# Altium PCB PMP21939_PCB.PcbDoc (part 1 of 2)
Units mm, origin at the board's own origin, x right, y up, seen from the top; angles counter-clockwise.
Board outline 80 x 87.63 mm, 4 copper layers (Top Layer, Signal Layer 1, Signal Layer 2, Bottom Layer), stack 1.565 mm thick; 129 components, 68 nets, 325 pads, 91 vias.
Unrouted connection lines stored in the file: 2.
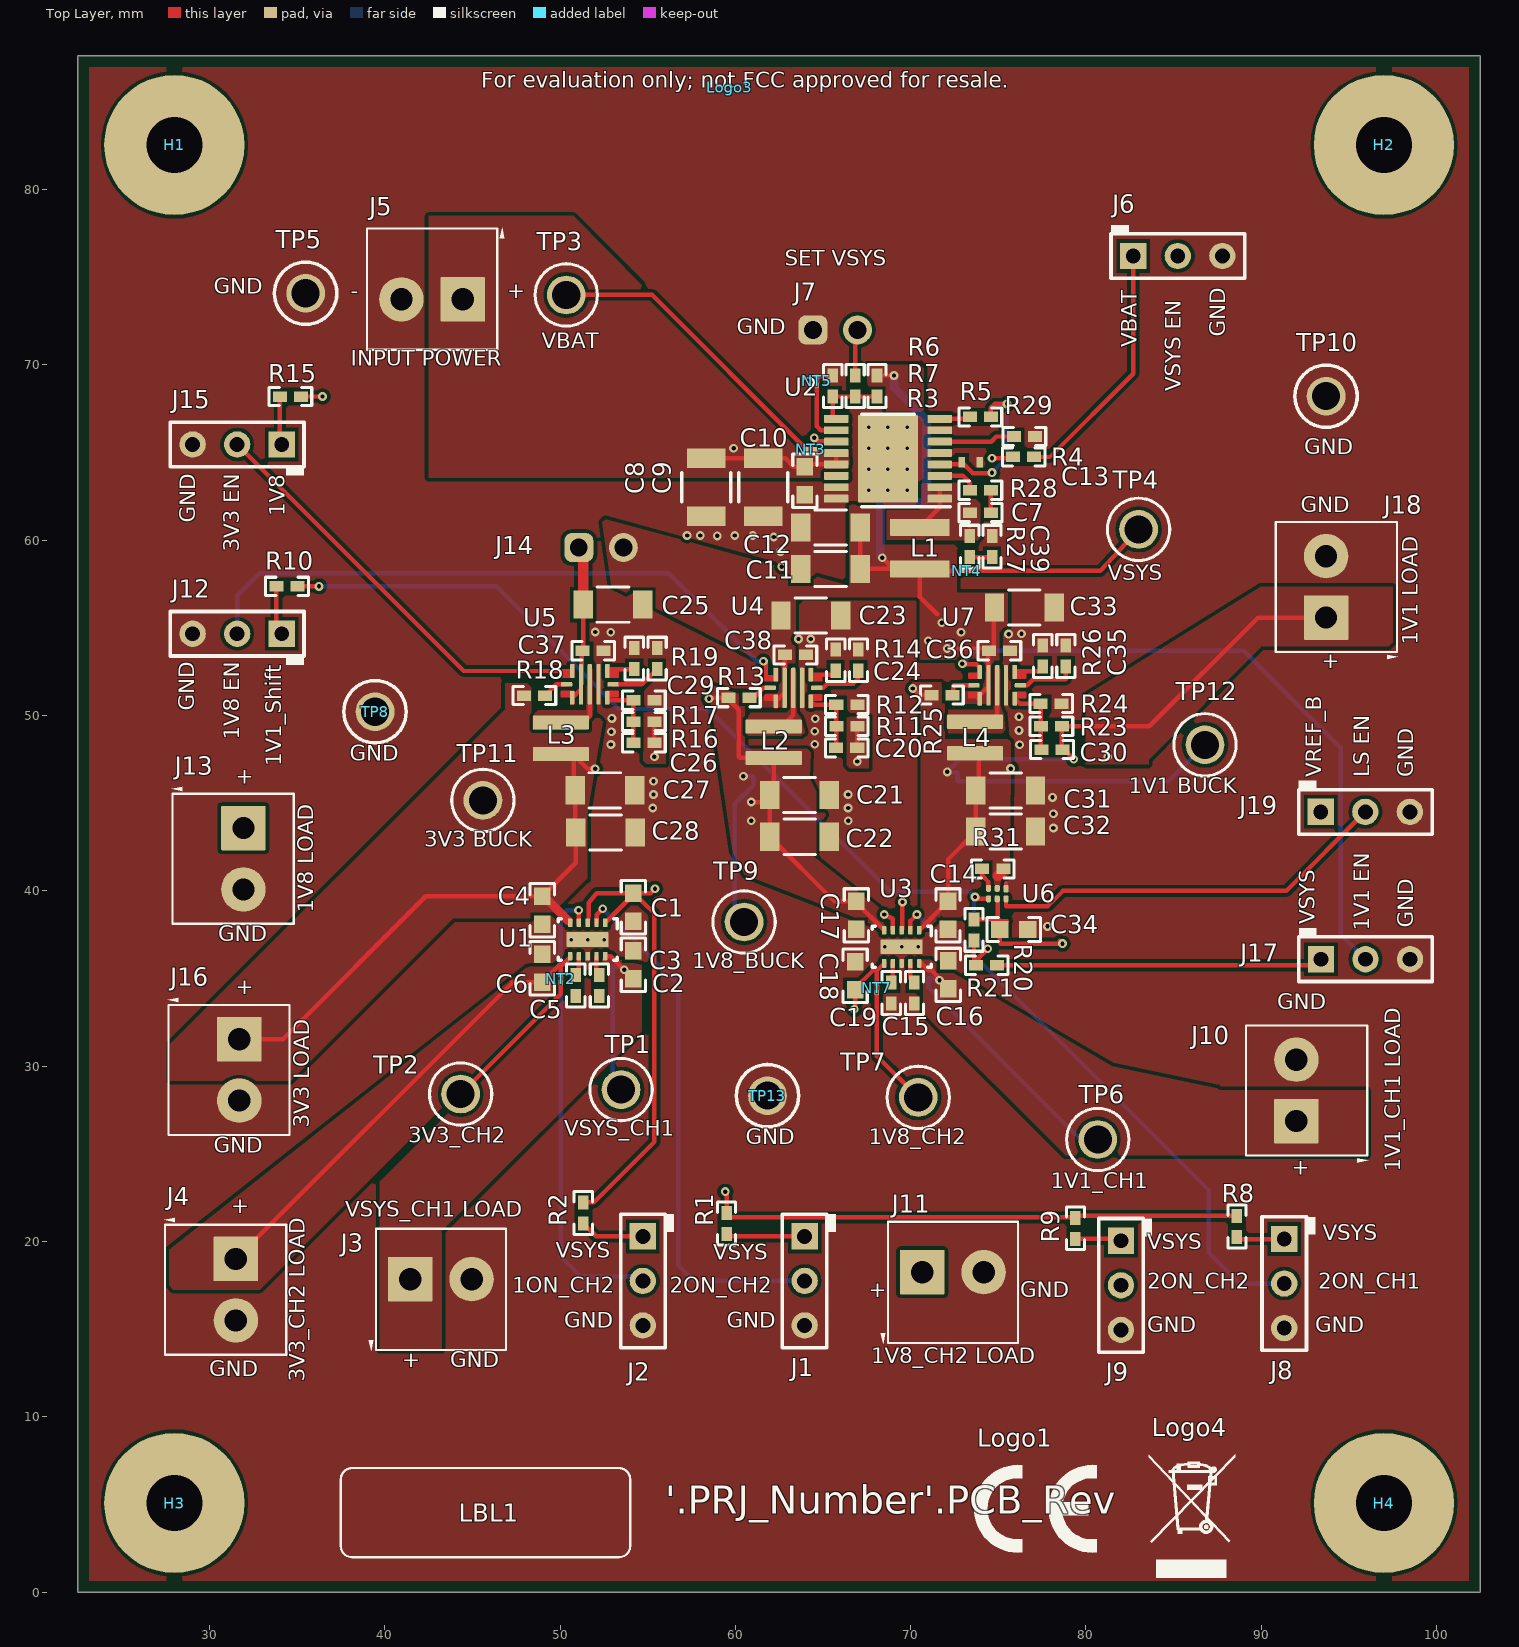
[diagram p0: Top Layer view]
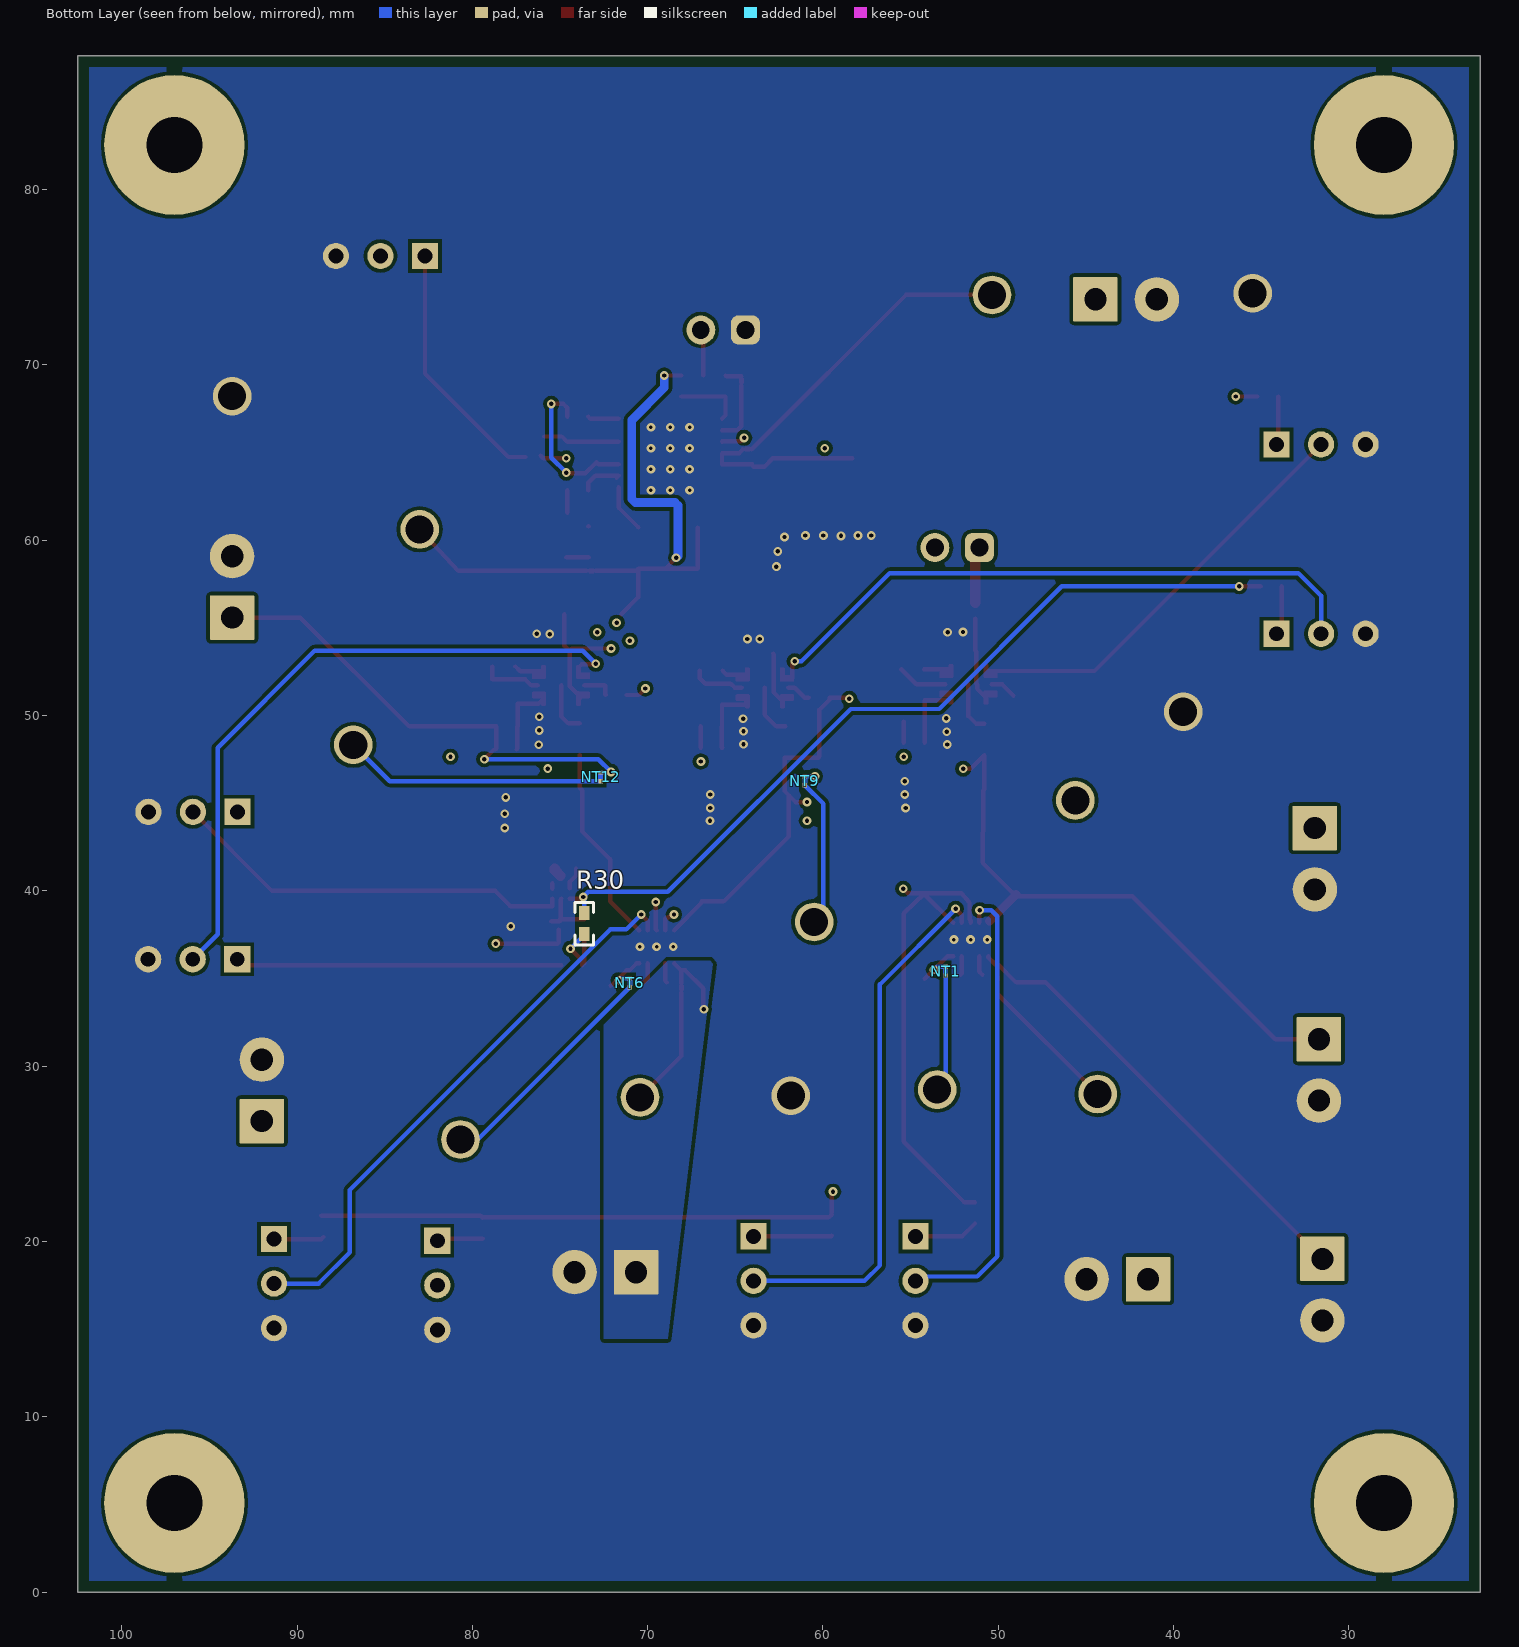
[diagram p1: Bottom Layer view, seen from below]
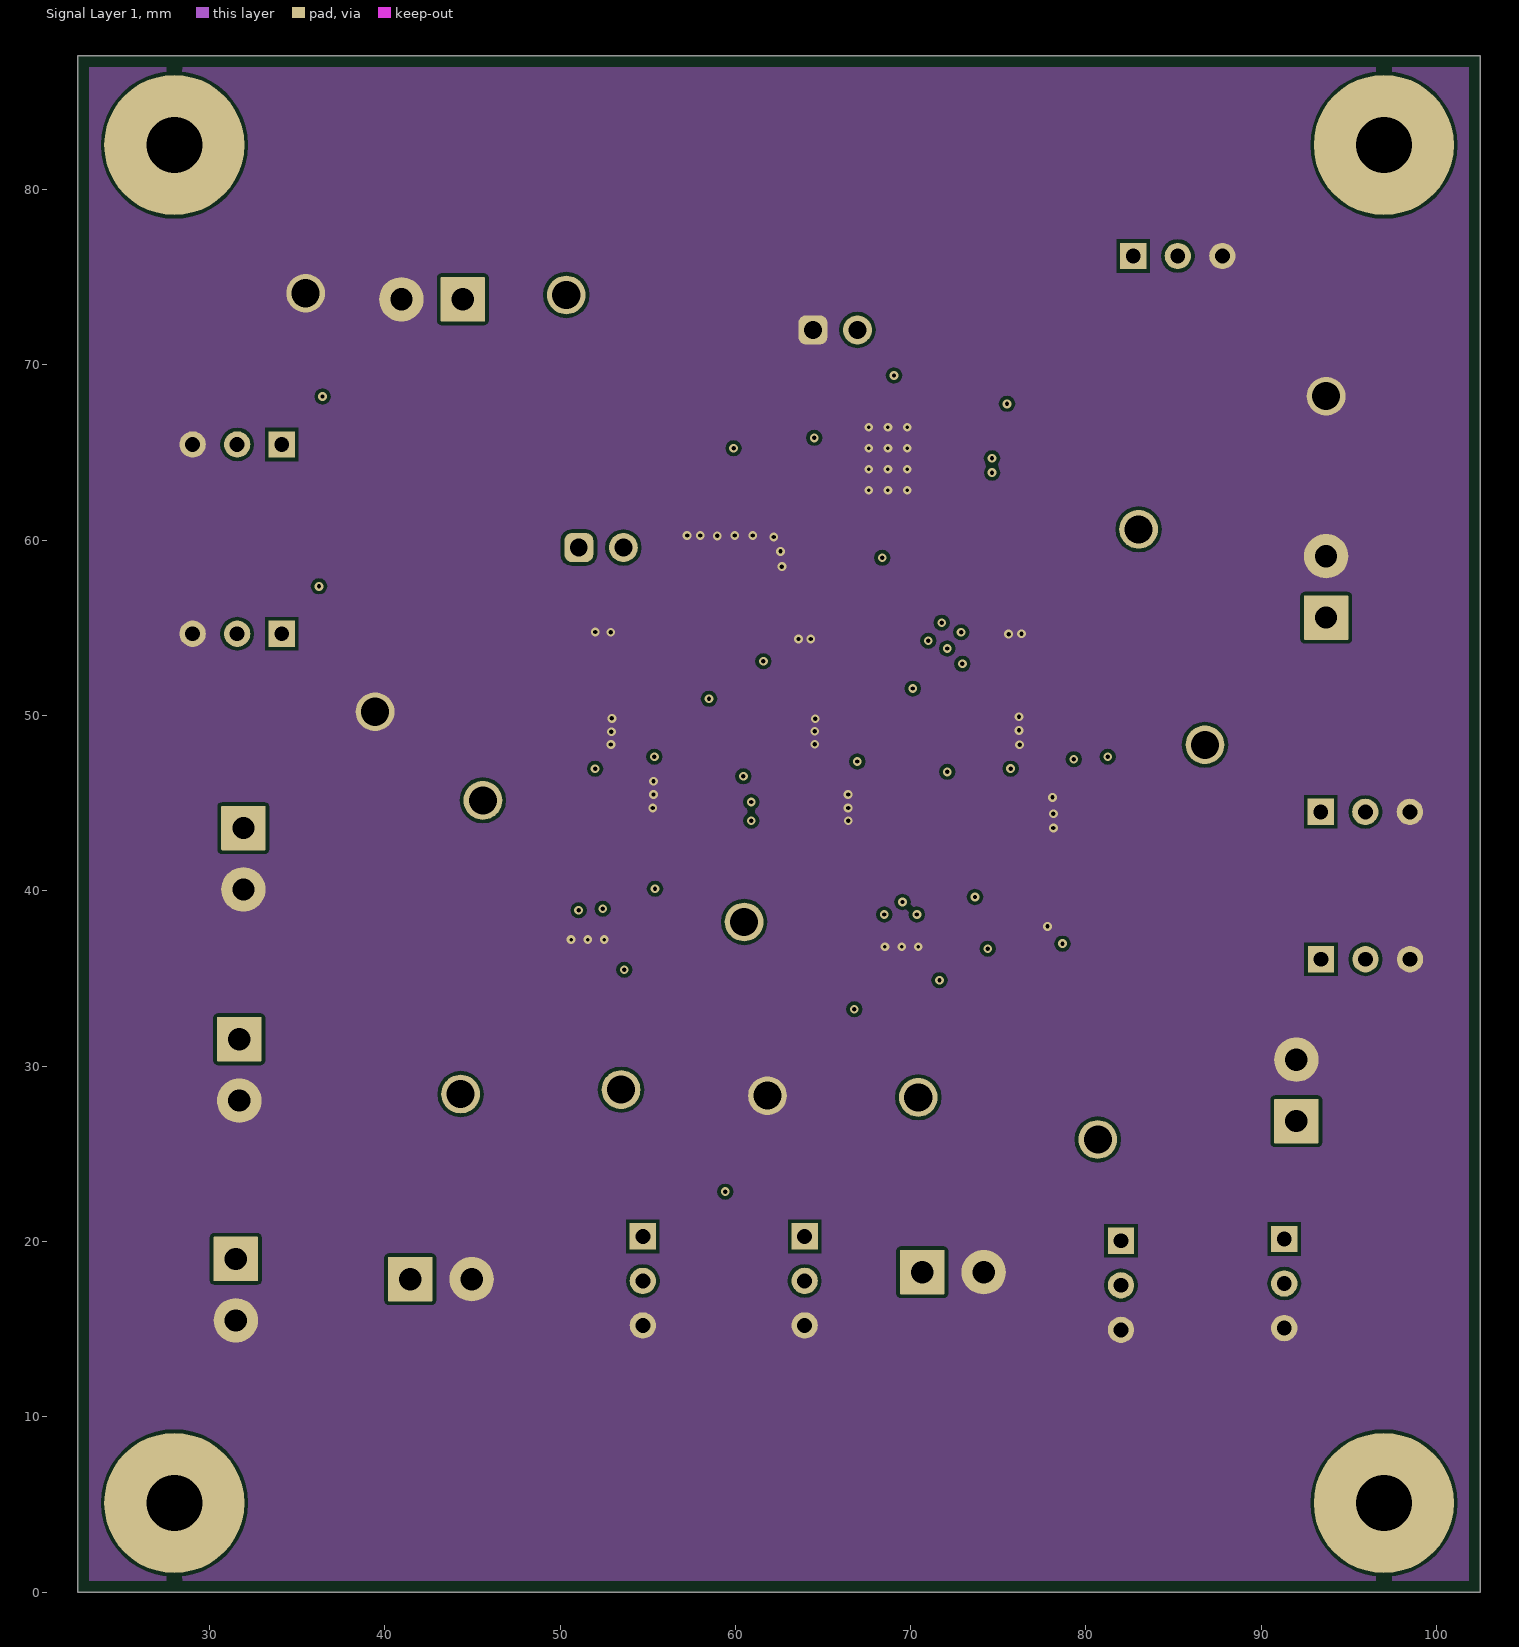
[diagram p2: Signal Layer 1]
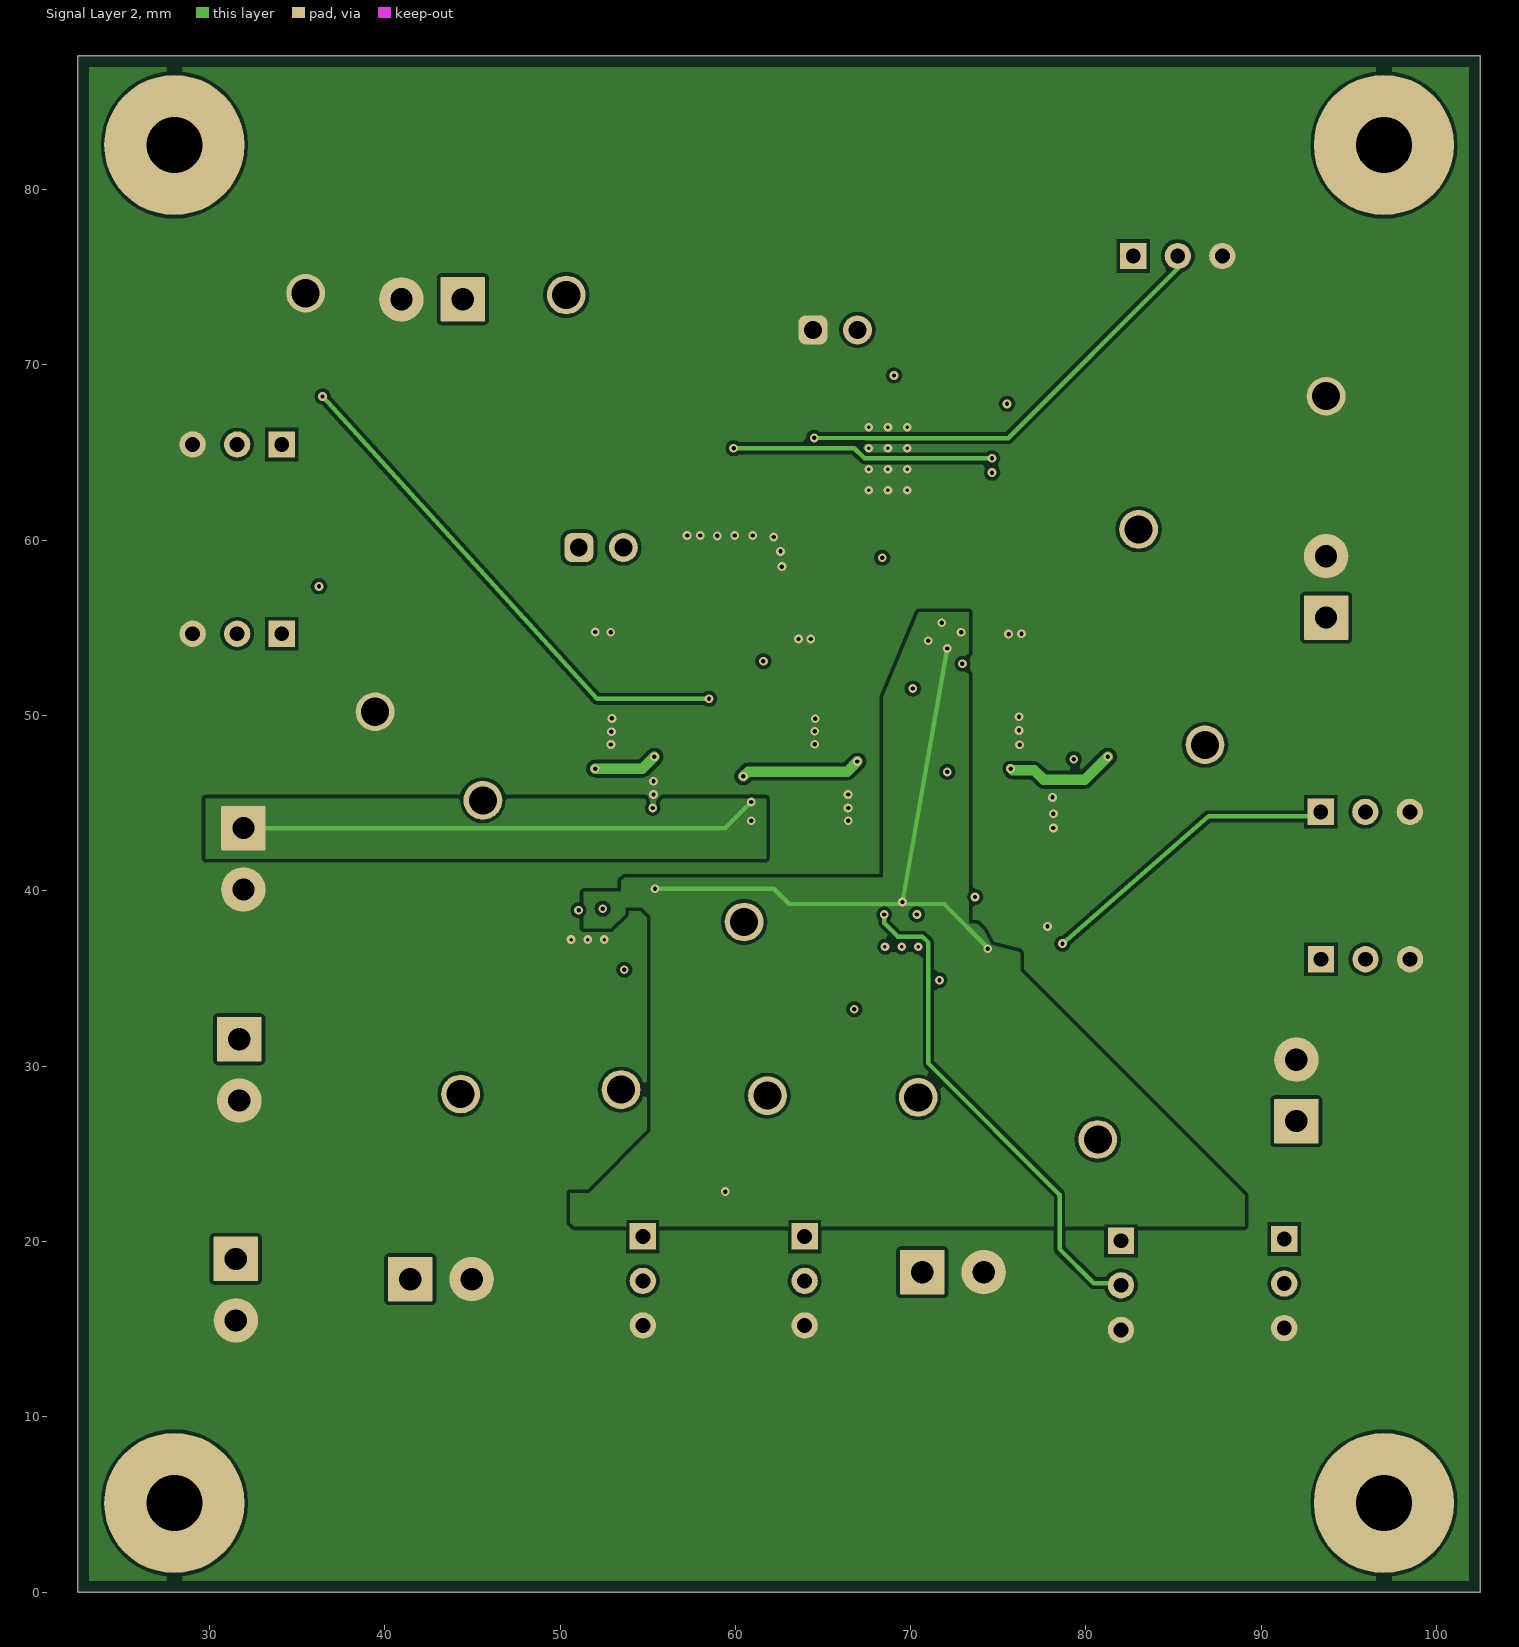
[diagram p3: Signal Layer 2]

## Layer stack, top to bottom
Top Solder: solder mask 0.0102, Solder Resist, Dk 3.5
Top Layer: signal copper 0.0356
Dielectric 2: dielectric 0.2032, Dk 4.2
Signal Layer 1: signal copper 0.0356
Dielectric1: core 1.016, FR-4, Dk 4.8
Signal Layer 2: signal copper 0.0356
Dielectric 3: dielectric 0.2032, Dk 4.2
Bottom Layer: signal copper 0.0356
Bottom Solder: solder mask 0.0102, Solder Resist, Dk 3.5

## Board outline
22.5,0 102.5,0 102.5,87.63 22.5,87.63

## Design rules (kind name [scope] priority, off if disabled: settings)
AcuteAngle [All] p1: minimum=4.50000000000000E+0001 checktracksonly=FALSE
AssemblyTestPointUsage [All] p1: valid=2
BoardOutlineClearance BoardOutlineClearance_MountingHoles [OnCopper and InComponentClass('Mounting Holes')] p1: gap=1 ignorepadtopadclearanceinfootprint=FALSE
BoardOutlineClearance BoardOutlineClearance_Poly [OnCopper and IsPoly] p2: gap=0.635 ignorepadtopadclearanceinfootprint=FALSE
BoardOutlineClearance [OnCopper and Not InComponentClass('Logo') and not InComponentClass('FiducialMark') and not InRegion(1000,500,4000,800) and not InPoly] p3: gap=1.905 ignorepadtopadclearanceinfootprint=FALSE
Clearance Clearance_Keepouts [((IsTrack Or IsArc) And Not InPoly) And IsFree and IsKeepOut vs ((IsTrack Or IsArc) And Not InPoly) And IsFree and IsKeepOut] p1: gap=0 ignorepadtopadclearanceinfootprint=FALSE
Clearance Clearance_Poly [InPolygon] p2: gap=0.2 ignorepadtopadclearanceinfootprint=TRUE
Clearance Clearance_FiducialMark [IsKeepOut and InComponentClass('FiducialMark') vs IsPad and InComponentClass('FiducialMark')] p3: gap=0 ignorepadtopadclearanceinfootprint=FALSE
Clearance [All] p4: gap=0.2 ignorepadtopadclearanceinfootprint=TRUE
ComponentClearance ComponentClearance_MountingHoles_FiducialMarks [InComponentClass('Mounting Holes') vs InComponentClass('FiducialMark')] p1: gap=1.27 collisioncheckmode=3 verticalgap=0.254 showdistances=FALSE
ComponentClearance ComponentClearance_Shunt [InComponentClass('Header') vs InComponentClass('Shunt')] p2: gap=0 collisioncheckmode=3 verticalgap=0 showdistances=FALSE
ComponentClearance ComponentClearance_Logo [InComponentClass('Logo')] p3: gap=1.27 collisioncheckmode=3 verticalgap=0.254 showdistances=FALSE
ComponentClearance ComponentClearance_ScrewToNut [(HasFootprint('NY PMS 440 0025 PH')) vs (HasFootprint('Keystone_1902C'))] p4: gap=0.127 collisioncheckmode=3 verticalgap=0.254 showdistances=FALSE
ComponentClearance ComponentClearance_MountingHoles [InComponentClass('Mounting Holes')] p5: gap=6.35 collisioncheckmode=3 verticalgap=2540 showdistances=FALSE
ComponentClearance ComponentClearance_SmallPassives [HasFootprint('0201*') or HasFootprint('0402*') or HasFootprint('0508') or HasFootprint('0603*') or HasFootprint('0612') or HasFootprint('0805*') or HasFootprint('0815*') or HasFootprint('0830*') or HasFootprint('1206*') or HasFootprint('1210*') or HasFootprint('1808*') or HasFootprint('1812*') or HasFootprint('1825*') or HasFootprint('2010*') or HasFootprint('2220*') or HasFootprint('2225*') or HasFootprint('2512*') or HasFootprint('2728*') or HasFootprint('3518*') vs HasFootprint('0201*') or HasFootprint('0402*') or HasFootprint('0508') or HasFootprint('0603*') or HasFootprint('0612') or HasFootprint('0805*') or HasFootprint('0815*') or HasFootprint('0830*') or HasFootprint('1206*') or HasFootprint('1210*') or HasFootprint('1808*') or HasFootprint('1812*') or HasFootprint('1825*') or HasFootprint('2010*') or HasFootprint('2220*') or HasFootprint('2225*') or HasFootprint('2512*') or HasFootprint('2728*') or HasFootprint('3518*')] p6: gap=0.38 collisioncheckmode=3 verticalgap=0.254 showdistances=FALSE
ComponentClearance ComponentClearance_THtoSMT [IsThruComponent vs IsSMTComponent] p7: gap=1.016 collisioncheckmode=3 verticalgap=0.762 showdistances=FALSE
ComponentClearance ComponentClearance_THtoTH [IsThruComponent vs IsThruComponent] p8: gap=0.762 collisioncheckmode=3 verticalgap=0.762 showdistances=FALSE
ComponentClearance [All] p9: gap=0.1 collisioncheckmode=3 verticalgap=0.1 showdistances=FALSE
DiffPairsRouting [All] p1: maxlimit=2.54 minlimit=0.254 mostfreqgap=0.254 toplayer_minwidth=0.381 toplayer_maxwidth=0.381 toplayer_prefwidth=0.381 midlayer1_minwidth=0.381 midlayer1_maxwidth=0.381 midlayer1_prefwidth=0.381 midlayer2_minwidth=0.381 midlayer2_maxwidth=0.381 midlayer2_prefwidth=0.381 bottomlayer_minwidth=0.381 bottomlayer_maxwidth=0.381 bottomlayer_prefwidth=0.381 maxuncoupledlength=25.4
FabricationTestPointUsage TestPointUsage [All] p1: valid=2 allowmultiple=FALSE
FabricationTestpoint Testpoint [All] p1: side=3 testpointundercomponent=TRUE minsize=1.016 maxsize=2.54 preferedsize=1.524 minholesize=0 maxholesize=1.016 preferedholesize=0.813 testpointgrid=0.025 allowsidetop=TRUE allowsidebottom=TRUE usegrid=TRUE gridtolerance=0
FanoutControl Fanout_LCC [IsLCC] p1: bgadir=Out bgaviamode=Centered fanoutstyle=Auto fanoutdirection=Alternating viagrid=0.025 // Fanout_LCC (Default Rule)
FanoutControl Fanout_BGA [IsBGA] p2: bgadir=Out bgaviamode=Centered fanoutstyle=Auto fanoutdirection=Alternating viagrid=0.025 // Fanout_BGA (Default Rule)
FanoutControl Fanout_Default [All] p4: bgadir=Out bgaviamode=Centered fanoutstyle=Auto fanoutdirection=Alternating viagrid=0.025 // Fanout_Default (Default Rule)
FanoutControl Fanout_Small [(CompPinCount < 5)] p5: bgadir=Out bgaviamode=Centered fanoutstyle=Auto fanoutdirection=OutThenIn viagrid=0.025 // Fanout_Small (Default Rule)
HoleSize [All] p1: absolutevalues=TRUE maxlimit=6.375 minlimit=0.2 maxpercent=80.000 minpercent=20.000
MinimumAnnularRing MinimumAnnularRing_ThermalPadVias [IsVia and InAnyComponent] p1: minimumring=0.15
MinimumAnnularRing [All] p2: minimumring=0.2
MinimumSolderMaskSliver MinimumSolderMaskSliver_Logo [InComponentClass('Logo') vs InComponentClass('Logo')] p1: minsoldermaskwidth=0.018
MinimumSolderMaskSliver [All] p2: minsoldermaskwidth=0.1
PlaneClearance [All] p1: clearance=0.1
PlaneConnect [All] p1: planeconnectstyle=Direct reliefexpansion=0.254 reliefentries=4 reliefconductorwidth=0.254 reliefairgap=0.254
PolygonConnect [All] p1: connectstyle=Direct reliefconductorwidth=0.254 reliefentries=4 polygonreliefangle="90 Angle" airgapwidth=0.254
RoutingVias ThermalPadVias [IsVia and InAnyComponent] p1: holewidth=0.2 width=0.5 viastyle="Through Hole" minholewidth=0.2 minwidth=0.5 maxholewidth=0.33 maxwidth=0.6
RoutingVias [All] p2: holewidth=0.406 width=0.864 viastyle="Through Hole" minholewidth=0.2 minwidth=0.66 maxholewidth=1.016 maxwidth=1.651
SilkToBoardRegionClearance [Not ((IsComment or IsDesignator) And (Hide <> 'False')) and not InRegion(1000,500,4000,800)] p1:
SilkToSilkClearance SilkToSilkClearance_Pb-FreeLogo [(HasFootprint('Pb-Free_Overlay_Medium') OR HasFootprint('Pb-Free_Overlay_Small')) vs (HasFootprint('Pb-Free_Overlay_Medium') OR HasFootprint('Pb-Free_Overlay_Small'))] p1: silktosilkclearance=0
SilkToSilkClearance [All] p2: silktosilkclearance=0.1
SilkToSolderMaskClearance SilkToComponentPadClearance [(IsPad or IsFill or IsRegion) and InAnycomponent] p1: minsilkscreentomaskgap=0.127 clearancetoexposedcopper=TRUE
SilkToSolderMaskClearance "Silk to Solder Mask Opening" [All] p2: minsilkscreentomaskgap=0.1 clearancetoexposedcopper=FALSE
SolderMaskExpansion [All] p1: expansion=0.05
UnRoutedNet [All] p1: checkbadconnections=TRUE
Width [All] p1: maxlimit=2.54 minlimit=0.152 preferedwidth=0.254 checkconnectedcopper=TRUE
13 further rules are at their usual default settings.

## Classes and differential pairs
component class "PMP21939_Load Converters": C20 C21 C22 C23 C24 C25 C26 C27 C28 C29 C30 C31 C32 C33 C34 C35 C36 C37 C38 J12 J13 J14 J15 J16 J17 J18 J19 L2 L3 L4 NT9 NT12 R10 R11 R12 R13 R14 R15 R16 R17 R18 R19 R20 R21 R23 R24 R25 R26 R30 R31 TP9 TP10 TP11 TP12 TP13 U4 U5 U6 U7
component class "PMP21939_Bus+Load Switches": C1 C2 C3 C4 C5 C6 C7 C8 C9 C10 C11 C12 C13 C14 C15 C16 C17 C18 C19 C39 J1 J2 J3 J4 J5 J6 J7 J8 J9 J10 J11 L1 NT1 NT2 NT3 NT4 NT5 NT6 NT7 R1 R2 R3 R4 R5 R6 R7 R8 R9 R27 R28 R29 TP1 TP2 TP3 TP4 TP5 TP6 TP7 TP8 U1 U2 U3
component class Header: J1 J2 J6 J7 J8 J9 J12 J14 J15 J17 J19
component class "Mounting Holes": H1 H2 H3 H4
component class Hardware: H1 H2 H3 H4 LBL1 Logo1 Logo3 Logo4
component class Label: LBL1

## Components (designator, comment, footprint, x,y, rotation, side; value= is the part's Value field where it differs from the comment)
C1 "GCM188R71C105MA64D" 0603 54.186,39.074 r270 top value=1uF
C2 "CGA2B2X7R1H102K050BA" 0402 52.244,34.601 r270 top value=1000pF
C3 "CGA3E2X7R1E104K080AA" 0603 54.186,35.78 r90 top value=0.1uF
C4 "GCM188R71C105MA64D" 0603 48.985,38.893 r270 top value=1uF
C5 "CGA2B2X7R1H102K050BA" 0402 50.899,34.605 r270 top value=1000pF
C6 "CGA3E2X7R1E104K080AA" 0603 48.985,35.579 r90 top value=0.1uF
C7 "C1005X7R1C224K050BC" 0402 73.985,61.578 r180 top value=0.22uF
C8 "CGA6P3X7R1H475K250AB" 1210_280 58.338,63.026 r270 top value=4.7uF
C9 "CGA6P3X7R1H475K250AB" 1210_280 61.588,63.026 r270 top value=4.7uF
C10 "CGA3E2X7R1E104K080AA" 0603 63.965,63.4 r270 top value=0.1uF
C11 "GCM31CR71A226KE02" 1206_180 65.432,58.366 r180 top value=22uF
C12 "GCM31CR71A226KE02" 1206_180 65.432,60.719 r180 top value=22uF
C13 "GCM155C71A105KE38D" 0402_070 73.432,64.45 r0 top value=1uF
C14 "GCM188R71C105MA64D" 0603 72.136,38.599 r270 top value=1uF
C15 "CGA2B2X7R1H102K050BA" 0402 70.219,34.176 r270 top value=1000pF
C16 "CGA3E2X7R1E104K080AA" 0603 72.146,35.205 r90 top value=0.1uF
C17 "GCM188R71C105MA64D" 0603 66.908,38.599 r270 top value=1uF
C18 "CGA3E2X7R1E104K080AA" 0603 66.834,35.155 r90 top value=0.1uF
C19 "CGA2B2X7R1H102K050BA" 0402 68.9,34.176 r270 top value=1000pF
C20 "CGA2B2NP01H220J050BA" 0402 66.357,48.152 r180 top value=22pF
C21 "GCM31CR71A226KE02" 1206_180 63.662,45.469 r0 top value=22uF
C22 "GCM31CR71A226KE02" 1206_180 63.667,43.088 r0 top value=22uF
C23 "GCM31CR71A226KE02" 1206_180 64.312,55.719 r0 top value=22uF
C24 "CGA2B3X7S2A472K050BB" 0402 67.026,53.157 r90 top value=4700pF
C25 "GCM31CR71A226KE02" 1206_180 53.024,56.324 r0 top value=22uF
C26 "CGA2B2NP01H220J050BA" 0402 54.786,48.448 r180 top value=22pF
C27 "GCM31CR71A226KE02" 1206_180 52.562,45.739 r0 top value=22uF
C28 "GCM31CR71A226KE02" 1206_180 52.597,43.333 r0 top value=22uF
C29 "CGA2B3X7S2A472K050BB" 0402 55.538,53.251 r90 top value=4700pF
C30 "CGA2B2NP01H220J050BA" 0402 78.063,48.064 r180 top value=22pF
C31 "GCM31CR71A226KE02" 1206_180 75.424,45.73 r0 top value=22uF
C32 "GCM31CR71A226KE02" 1206_180 75.421,43.38 r0 top value=22uF
C33 "GCM31CR71A226KE02" 1206_180 76.492,56.176 r0 top value=22uF
C34 "CGA3E2X7R1E104K080AA" 0603 75.879,37.796 r0 top value=0.1uF
C35 "CGA2B3X7S2A472K050BB" 0402 78.858,53.399 r90 top value=4700pF
C36 "CGA2B3X7R1H104K050BB" 0402 75.067,53.699 r0 top value=0.1uF
C37 "CGA2B3X7R1H104K050BB" 0402 51.894,53.699 r0 top value=0.1uF
C38 "CGA2B3X7R1H104K050BB" 0402 63.426,53.457 r0 top value=0.1uF
C39 "GCM155R71H391KA37D" 0402 74.647,59.637 r270 top value=390pF
H1 "NY PMS 440 0025 PH" "NY PMS 440 0025 PH"#1 5.08,82.55 r0 top
H2 "NY PMS 440 0025 PH" "NY PMS 440 0025 PH"#2 120.65,82.55 r0 top
H3 "NY PMS 440 0025 PH" "NY PMS 440 0025 PH"#1 5.08,5.08 r0 top locked
H4 "NY PMS 440 0025 PH" "NY PMS 440 0025 PH"#2 120.65,5.08 r0 top
J1 "800-10-003-10-001000" Mill-Max_800-10-003-10-001000 63.958,17.752 r270 top
J2 "800-10-003-10-001000" Mill-Max_800-10-003-10-001000 54.724,17.75 r270 top
J3 "ED555/2DS" TERM_BLK_ED555-2DS 41.454,17.852 r0 top
J4 "ED555/2DS" TERM_BLK_ED555-2DS 31.508,19.002 r270 top
J5 "ED555/2DS" TERM_BLK_ED555-2DS 44.458,73.744 r180 top
J6 "800-10-003-10-001000" Mill-Max_800-10-003-10-001000 85.243,76.219 r0 top
J7 "TSW-102-07-G-S" TSW-102-07-G-S 65.696,72 r0 top
J8 "800-10-003-10-001000" Mill-Max_800-10-003-10-001000 91.316,17.597 r270 top
J9 "800-10-003-10-001000" Mill-Max_800-10-003-10-001000 82,17.5 r270 top
J10 "ED555/2DS" TERM_BLK_ED555-2DS 92.008,26.865 r90 top
J11 "ED555/2DS" TERM_BLK_ED555-2DS 70.661,18.25 r0 top
J12 "800-10-003-10-001000" Mill-Max_800-10-003-10-001000 31.584,54.668 r180 top
J13 "ED555/2DS" TERM_BLK_ED555-2DS 31.939,43.585 r270 top
J14 "TSW-102-07-G-S" TSW-102-07-G-S 52.344,59.586 r0 top
J15 "800-10-003-10-001000" Mill-Max_800-10-003-10-001000 31.584,65.468 r180 top
J16 "ED555/2DS" TERM_BLK_ED555-2DS 31.703,31.541 r270 top
J17 "800-10-003-10-001000" Mill-Max_800-10-003-10-001000 95.953,36.101 r0 top
J18 "ED555/2DS" TERM_BLK_ED555-2DS 93.703,55.589 r90 top
J19 "800-10-003-10-001000" Mill-Max_800-10-003-10-001000 95.941,44.509 r0 top
L1 "XEL4020-152MEB" XEL4020 70.528,59.551 r270 top value=1.5uH
L2 "XEL3520-471ME" FP-XEL3520-471ME_SMD2-MFG 62.191,48.482 r270 top
L3 "XEL3520-561ME" FP-XEL3520-561ME_SMT_IND_3MM2_3MM5-MFG 50.049,48.702 r270 top
L4 "XEL3520-471ME" FP-XEL3520-471ME_SMD2-MFG 73.674,48.748 r270 top
LBL1 "THT-14-423-10" Label_650x200 45.75,4.531 r0 top
Logo1 "CE Mark" CE_Mark_5mm 77.124,4.75 r0 top
Logo3 "FCC disclaimer" FCC_disclaimer 59.69,85.852 r0 top
Logo4 "WEEE logo" WEEE_Minimum 86,5.204 r0 top
NT1 "Net-Tie" Net-Tie_10mil 53,35.426 r270 bottom net-tie
NT2 "Net-Tie" Net-Tie_10mil 50.052,35 r270 top net-tie
NT3 "Net-Tie" Net-Tie_10mil 64.31,65.2 r0 top net-tie
NT4 "Net-Tie" Net-Tie_10mil 73.211,58.25 r0 top net-tie
NT5 "Net-Tie" Net-Tie_10mil 64.658,69.097 r270 top net-tie
NT6 "Net-Tie" Net-Tie_10mil 71.016,34.75 r270 bottom net-tie
NT7 "Net-Tie" Net-Tie_10mil 68.076,34.476 r270 top net-tie
NT9 "Net-Tie" Net-Tie_10mil 61.036,46.28 r270 bottom net-tie
NT12 "Net-Tie" Net-Tie_10mil 72.678,46.5 r270 bottom net-tie
R1 "ERJPA2F1002X" 0402 59.5,21.026 r90 top value=10.0k
R2 "ERJPA2F1002X" 0402 51.327,21.626 r90 top value=10.0k
R3 "RMCF0402FT100K" 0402 68.084,68.801 r90 top value=100k
R4 "ERJPA2F1002X" 0402 76.452,64.756 r180 top value=10.0k
R5 "RMCF0402FT100K" 0402 73.979,67.036 r0 top value=100k
R6 "CRCW040243K2FKED" 0402 65.559,68.801 r270 top value=43.2k
R7 "CRCW040259K0FKED" 0402 66.834,68.801 r270 top value=59.0k
R8 "ERJPA2F1002X" 0402 88.618,20.855 r90 top value=10.0k
R9 "ERJPA2F1002X" 0402 79.407,20.75 r90 top value=10.0k
R10 "ERJPA2F1002X" 0402 34.425,57.371 r0 top value=10.0k
R11 "CRCW040280K6FKED" 0402 66.362,49.388 r0 top value=80.6k
R12 "CRCW040240K2FKED" 0402 66.359,50.627 r180 top value=40.2k
R13 "RMCF0402FT100K" 0402 60.201,51.021 r180 top value=100k
R14 "CRCW04028K06FKED" 0402 65.727,53.157 r270 top value=8.06k
R15 "ERJPA2F1002X" 0402 34.62,68.201 r0 top value=10.0k
R16 "CRCW040288K7FKED" 0402 54.786,49.655 r0 top value=88.7k
R17 "CRCW040219K6FKED" 0402 54.786,50.877 r180 top value=19.6k
R18 "RMCF0402FT100K" 0402 48.541,51.142 r180 top value=100k
R19 "CRCW04028K06FKED" 0402 54.236,53.251 r270 top value=8.06k
R20 "ERJ-2RKF2003X" 0402 73.617,37.776 r270 top value=200k
R21 "ERJPA2F1002X" 0402 74.342,35.755 r180 top value=10.0k
R23 "CRCW040239K2FKED" 0402 78.032,49.389 r0 top value=39.2k
R24 "RC0402FR-0747KL" 0402 78.022,50.686 r180 top value=47.0k
R25 "RMCF0402FT100K" 0402 71.786,51.173 r180 top value=100k
R26 "CRCW04028K06FKED" 0402 77.543,53.399 r270 top value=8.06k
R27 "CRCW04023R01FKED" 0402 73.372,59.637 r270 top value=3.01
R28 "CRCW04020000Z0EDHP" 0402 73.982,62.851 r180 top value=0
R29 "ERJPA2F1002X" 0402 76.492,65.92 r0 top value=10.0k
R30 "CRCW04021K00FKED" 0402 73.617,38.127 r270 bottom value=1.00k
R31 "CRCW04021K00FKED" 0402 74.686,41.25 r0 top value=1.00k
TP1 "5129" Keystone5129 53.481,28.664 r270 top
TP2 "5129" Keystone5129 44.33,28.41 r180 top
TP3 "5129" Keystone5129 50.355,73.994 r270 top
TP4 "5129" Keystone5129 83.005,60.624 r270 top
TP5 "5011" Keystone5011 35.488,74.092 r270 top
TP6 "5129" Keystone5129 80.678,25.817 r270 top
TP7 "5129" Keystone5129 70.436,28.219 r0 top
TP8 "5011" Keystone5011 39.449,50.219 r270 top
TP9 "5129" Keystone5129 60.501,38.226 r270 top
TP10 "5011" Keystone5011 93.703,68.219 r270 top
TP11 "5129" Keystone5129 45.601,45.161 r270 top
TP12 "5129" Keystone5129 86.794,48.332 r270 top
TP13 "5011" Keystone5011 61.834,28.317 r270 top
U1 "TPS22968NQDMGRQ1" DMG0010A 51.579,37.226 r270 top
U2 "LM63635DQPWPTQ1" PWP0016K_N 68.71,64.651 r180 top
U3 "TPS22968NQDMGRQ1" DMG0010A 69.489,36.81 r270 top
U4 "TPS62810QWRWYRQ1" RWY0009A 63.312,51.58 r90 top
U5 "TPS62810QWRWYRQ1" RWY0009A 51.699,51.782 r90 top
U6 "LSF0101DRYR" DRY0006A 74.942,39.844 r270 top
U7 "TPS62810QWRWYRQ1" RWY0009A 74.942,51.724 r90 top

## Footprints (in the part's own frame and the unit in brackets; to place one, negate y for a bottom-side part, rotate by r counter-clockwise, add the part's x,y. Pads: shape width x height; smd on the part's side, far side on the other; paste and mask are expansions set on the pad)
0402 [mm] "0402 from SM-752 data"
  rect 0.8x0.6 smd: 1(-0.6,0) 2(0.6,0)
  silkscreen extent -1.22,-0.52 1.22,0.52, body extent -0.55,-0.3 0.55,0.3, height 0.6
0402_070 [mil] "SMD, 2-Leads, Body 1.2x0.7mm, Height 0.7mm"
  rect 15x24 smd: 1(-20,0) 2(20,0)
  body extent -24,-14 24,14, height 28
0603 [mm] "0603 from SM-752 data"
  rect 1x0.95 smd: 1(-0.8,0) 2(0.8,0)
  silkscreen extent -1.52,-0.69 1.52,0.69, body extent -0.87,-0.47 0.87,0.47, height 1
1206_180 [mm] "1206_180"
  rect 1.1x1.6 smd: 1(-1.7,0) 2(1.7,0)
  silkscreen extent -0.9,-1 0.9,1, body extent -1.75,-0.95 1.75,0.95, height 1.8
1210_280 [mm] "SMD, 2-Leads, Body 3.6x2.8mm, Height 2.8mm"
  rect 1.1x2.2 smd: 1(-1.65,0) 2(1.65,0)
  silkscreen extent -0.84,-1.4 0.84,1.4, body extent -1.8,-1.4 1.8,1.4, height 2.8
CE_Mark_5mm [mm] "Minimum text height for CE Mark"
  silkscreen extent -3.5,-2.5 3.5,2.5
DMG0010A [mm] "SON, 10-Leads, Body 2.1x3.1mm, Pitch 0.5mm, Thermal Pad 2.4x0.8mm"
  rrect40% 0.5x0.25 smd: 1(-0.95,1) 2(-0.95,0.5) 3(-0.95,0) 4(-0.95,-0.5) 5(-0.95,-1) 6(0.95,-1) 7(0.95,-0.5) 8(0.95,0) 9(0.95,0.5) 10(0.95,1)
  rrect12% 0.8x1.08 on Top Paste: 11(0,0.64) 11(0,-0.64)
  rrect12% 0.84x2.4 smd paste-0.42: 11(0,0)
  silkscreen extent -1.18,-1.68 1.17,1.68, body extent -1,-1.5 1,1.5, height 0.81
DRY0006A [mm] "USON-6"
  rrect67% 0.45x0.3 smd paste-0.05 mask-0.05: 1(-0.275,0.5)
  rrect67% 0.4x0.3 smd paste-0.05 mask-0.05: 2(-0.3,0) 3(-0.3,-0.5) 4(0.3,-0.5) 5(0.3,0) 6(0.3,0.5)
  body extent -0.5,-0.72 0.5,0.73, height 0.58
FCC_disclaimer [mm]
FP-XEL3520-471ME_SMD2-MFG [mm]
  rrect12% 0.81x3.2 smd paste+0 mask+0: 1(-0.9,0) 2(0.9,0)
  body extent -1.78,-1.92 1.78,1.92, height 0.25
FP-XEL3520-561ME_SMT_IND_3MM2_3MM5-MFG [mm]
  rrect12% 0.81x3.2 smd paste+0 mask+0: 1(-0.9,0) 2(0.9,0)
  body extent -1.78,-1.92 1.78,1.92, height 0.25
Keystone5011 [mil] "Keystone Multipurpose loops"
  round 87 hole 63: 1(0,0)
  silkscreen extent -70,-70 70,70, body extent -63,-63 63,62, height 319
Keystone5129 [mil] "Keystone Multipurpose loops"
  round 87 hole 63: 1(0,0)
  silkscreen extent -70,-70 70,70, body extent -63,-63 63,62, height 319
Label_650x200 [mil] "Thermal Transfer Label"
  round 1 on Mech13: 0(0,0)
  silkscreen extent -325,-100 325,100, body extent -325,-100 325,100, height 1
Mill-Max_800-10-003-10-001000 [mm] "Mill-Max"
  rect 1.5x1.5 hole 0.85: 1(-2.54,0)
  round 1.5 hole 0.85: 2(0,0) 3(2.54,0)
  silkscreen extent -3.81,-1.27 3.81,1.78, body extent -3.81,-1.27 3.81,1.27, height 8.13
Net-Tie_10mil [mil] "10mil net tie, no solder mask opening, no solder paste"
  rect 10x10 smd paste-5 mask-5: 1(-10,0) 2(10,0)
  Top Layer region: -6,5 6,5 6,-5 -6,-5
"NY PMS 440 0025 PH"#1 [mm] "4-40 nylon screw and mounting hole"
  round 8 hole 3.2: 1(22.92,0)
  body extent -3.3,-3.3 3.3,3.3, height 2.69
"NY PMS 440 0025 PH"#2 [mm] "4-40 nylon screw and mounting hole"
  round 8 hole 3.2: 1(-23.65,0)
  body extent -3.3,-3.3 3.3,3.3, height 2.69
PWP0016K_N [mm] "TSSOP-16"
  rrect22% 1.4x0.45 smd: 1(-2.95,2.275) 2(-2.95,1.625) 3(-2.95,0.975) 4(-2.95,0.325) 5(-2.95,-0.325) 6(-2.95,-0.975) 7(-2.95,-1.625) 8(-2.95,-2.275) 9(2.95,-2.275) 10(2.95,-1.625) 11(2.95,-0.975) 12(2.95,-0.325) 13(2.95,0.325) 14(2.95,0.975) 15(2.95,1.625) 16(2.95,2.275)
  rrect3% 3.4x5 smd paste-1.7 mask-1.7: 17(0,0)
  rrect4% 2.46x2.31 on Top Paste: 17(0,0)
  rrect4% 2.46x2.31 on Top Solder: 17(0,0)
  silkscreen extent -3.55,-2.55 1.5,2.75, body extent -3.21,-2.5 3.21,2.5, height 1
RWY0009A [mm] "VQFN-HR-9"
  rrect40% 0.775x0.25 smd paste-0.2: 1(-0.761,1) 5(-0.761,-1) 7(0.761,-1) 8(0.761,1)
  rrect40% 1.05x0.25 on Top Paste: 2(-0.625,0.5) 2(0.625,0.5) 3(-0.625,0) 3(0.625,0) 4(-0.625,-0.5) 4(0.625,-0.5)
  rrect40% 2.3x0.25 smd paste-0.5: 2(0,0.5) 3(0,0) 4(0,-0.5)
  rrect40% 0.25x0.65 smd: 6(0,-1.325) 9(0,1.325)
  Top Layer region: -1.15,0.925 -1.15,1.075 -1.146,1.094 -1.135,1.11 -1.119,1.121 -1.1,1.125 -1.1,1.125 -0.775,1.125 -0.756,1.129 -0.74,1.14 -0.729,1.156 -0.725,1.175 -0.725,1.175 -0.725,1.6 -0.721,1.619 -0.71,1.635 -0.694,1.646 -0.675,1.65 -0.675,1.65 -0.425,1.65 -0.406,1.646 -0.39,1.635 -0.379,1.619 -0.375,1.6 -0.375,1.6 -0.375,0.925 -0.379,0.906 -0.39,0.89 -0.406,0.879 -0.425,0.875 -0.425,0.875 -1.1,0.875 -1.119,0.879 -1.135,0.89 -1.146,0.906 -1.15,0.925
  Top Layer region: 0.375,0.925 0.375,1.6 0.379,1.619 0.39,1.635 0.406,1.646 0.425,1.65 0.425,1.65 0.675,1.65 0.694,1.646 0.71,1.635 0.721,1.619 0.725,1.6 0.725,1.6 0.725,1.175 0.729,1.156 0.74,1.14 0.756,1.129 0.775,1.125 0.775,1.125 1.1,1.125 1.119,1.121 1.135,1.11 1.146,1.094 1.15,1.075 1.15,1.075 1.15,0.925 1.146,0.906 1.135,0.89 1.119,0.879 1.1,0.875 1.1,0.875 0.425,0.875 0.406,0.879 0.39,0.89 0.379,0.906 0.375,0.925
  Top Layer region: 0.375,-1.6 0.379,-1.619 0.39,-1.635 0.406,-1.646 0.425,-1.65 0.425,-1.65 0.675,-1.65 0.694,-1.646 0.71,-1.635 0.721,-1.619 0.725,-1.6 0.725,-1.6 0.725,-1.175 0.729,-1.156 0.74,-1.14 0.756,-1.129 0.775,-1.125 0.775,-1.125 1.1,-1.125 1.119,-1.121 1.135,-1.11 1.146,-1.094 1.15,-1.075 1.15,-1.075 1.15,-0.925 1.146,-0.906 1.135,-0.89 1.119,-0.879 1.1,-0.875 1.1,-0.875 0.425,-0.875 0.406,-0.879 0.39,-0.89 0.379,-0.906 0.375,-0.925 0.375,-0.925
  Top Layer region: -1.1,-1.125 -1.119,-1.121 -1.135,-1.11 -1.146,-1.094 -1.15,-1.075 -1.15,-1.075 -1.15,-0.925 -1.146,-0.906 -1.135,-0.89 -1.119,-0.879 -1.1,-0.875 -1.1,-0.875 -0.425,-0.875 -0.406,-0.879 -0.39,-0.89 -0.379,-0.906 -0.375,-0.925 -0.375,-0.925 -0.375,-1.6 -0.379,-1.619 -0.39,-1.635 -0.406,-1.646 -0.425,-1.65 -0.425,-1.65 -0.675,-1.65 -0.694,-1.646 -0.71,-1.635 -0.721,-1.619 -0.725,-1.6 -0.725,-1.6 -0.725,-1.175 -0.729,-1.156 -0.74,-1.14 -0.756,-1.129 -0.775,-1.125 -0.775,-1.125
  body extent -1,-1.5 1,1.5, height 1
TERM_BLK_ED555-2DS [mil]
  rrect4% 100x100 hole 50: 1(0,0)
  round 100 hole 50: 2(138,0)
  silkscreen extent -93,-161 215,113, body extent -69,-150 207,106, height 323
TSW-102-07-G-S [mm] "Samtec 100mil, 1x2, 230 mil above insulator"
  rrect50% 1.65x1.65 hole 1.016: 1(-1.27,0)
  round 1.65 hole 1.016: 2(1.27,0)
  body extent -2.54,-1.27 2.54,1.27, height 8.38
WEEE_Minimum [mm] "WEEElie bin"
  silkscreen extent -2.42,-4.38 2.52,2.65
XEL4020 [mm] "SMD, 2-Leads, Body 4x4mm, Pitch 2.37mm"
  rrect10% 0.98x3.4 smd: 1(-1.185,0) 2(1.185,0)
  body extent -2.15,-2.15 2.15,2.15, height 2.1

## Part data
C1 C4 C14 C17: library part CMP-0007137-1, "CAP, CERM, 1 uF, 16 V, +/- 20%, X7R, AEC-Q200 Grade 1, 0603", Cap_Case=0603, Manufacturer=MuRata, TempCo=X7R, Tolerance_%=20%, Value1=Unknown, Value2=16V, ValueDisplayed=1uF
C2 C5 C15 C19: library part CMP-0006314-2, "CAP, CERM, 1000 pF, 50 V, +/- 10%, X7R, AEC-Q200 Grade 1, 0402", Cap_Case=0402, Manufacturer=TDK, Supplier Part Number 1=445-5605-1-ND, TempCo=X7R, Tolerance_%=10%, Value1="2.25564 ohm", Value2=50V, ValueDisplayed=1000pF
C3 C6 C10 C16 C18 C34: library part CMP-0007077-5, "CAP, CERM, 0.1 uF, 25 V, +/- 10%, X7R, AEC-Q200 Grade 1, 0603", Cap_Case=0603, Manufacturer=TDK, Supplier Part Number 1=445-5667-1-ND, TempCo=X7R, Tolerance_%=10%, Value1=Unknown, Value2=25V, ValueDisplayed=0.1uF
C7: library part CMP-0006293-1, "CAP, CERM, 0.22 uF, 16 V, +/- 10%, X7R, 0402", Cap_Case=0402, Manufacturer=TDK, Supplier Part Number 1=445-5936-1-ND, TempCo=X7R, Tolerance_%=10%, Value1=Unknown, Value2=16V, ValueDisplayed=0.22uF
C8 C9: library part CMP-0009162-2, "CAP, CERM, 4.7 uF, 50 V, +/- 10%, X7R, AEC-Q200 Grade 1, 1210", Cap_Case=1210_280, Manufacturer=TDK, Supplier Part Number 1=445-6999-1-ND, TempCo=X7R, Tolerance_%=10%, Value1="0.003166 ohm", Value2=50V, ValueDisplayed=4.7uF
C11 C12 C21 C22 C23 C25 C27 C28 C31 C32 C33: library part CMP-0008811-1, "CAP, CERM, 22 uF, 10 V, +/- 10%, X7R, AEC-Q200 Grade 1, 1206", Cap_Case=1206, Manufacturer=MuRata, TempCo=X7R, Tolerance_%=10%, Value1=Unknown, Value2=10V, ValueDisplayed=22uF
C13: library part CMP-0006349-1, "CAP, CERM, 1 uF, 10 V, +/- 10%, X7S, AEC-Q200 Grade 1, 0402", Cap_Case=0402, Manufacturer=MuRata, Supplier Part Number 1=81-GCM155C71A105KE8D, TempCo=X7S, Tolerance_%=10%, Value1=Unknown, Value2=10V, ValueDisplayed=1uF
C20 C26 C30: library part CMP-0006311-2, "CAP, CERM, 22 pF, 50 V, +/- 5%, C0G/NP0, AEC-Q200 Grade 1, 0402", Cap_Case=0402, Manufacturer=TDK, Supplier Part Number 1=445-12130-1-ND, TempCo=C0G/NP0, Tolerance_%=5%, Value1=Unknown, Value2=50V, ValueDisplayed=22pF
C24 C29 C35: library part CMP-0006337-2, "CAP, CERM, 4700 pF, 100 V, +/- 10%, X7S, AEC-Q200 Grade 1, 0402", Cap_Case=0402, Manufacturer=TDK, Supplier Part Number 1=445-6908-1-ND, TempCo=X7S, Tolerance_%=10%, Value1="0.685549 ohm", Value2=100V, ValueDisplayed=4700pF
C36 C37 C38: library part CMP-0006325-2, "CAP, CERM, 0.1 uF, 50 V, +/- 10%, X7R, AEC-Q200 Grade 1, 0402", Cap_Case=0402, Manufacturer=TDK, Supplier Part Number 1=445-6899-1-ND, TempCo=X7R, Tolerance_%=10%, Value1="0.039064 ohm", Value2=50V, ValueDisplayed=0.1uF
C39: library part CMP-0080703-2, "CAP, CERM, 390 pF, 50 V,+/- 10%, X7R, AEC-Q200 Grade 1, 0402", Cap_Case=0402, Manufacturer=MuRata, Supplier Part Number 1=81-GCM155R71H391KA7D, TempCo=X7R, Tolerance_%=10%, Value2=50V, ValueDisplayed=390pF
H1 H2 H3 H4: library part CMP-0003617-1, "Machine Screw, Round, #4-40 x 1/4, Nylon, Philips panhead", Manufacturer="B&F Fastener Supply", Supplier Part Number 1=H542-ND
J1 J2 J6 J8 J9 J12 J15 J17 J19: library part CMP-0055086-1, "Header, 100mil, 3x1, TH", Manufacturer=Mill-Max, Supplier Part Number 1=ED7203-ND
J3 J4 J5 J10 J11 J13 J16 J18: library part CMP-0074913-1, "Terminal Block, 3.5mm Pitch, 2x1, TH", Color=Grey, Current_A=6A, Manufacturer="On-Shore Technology", Supplier Part Number 1=ED1514-ND, Voltage_V=150V
J7 J14: library part CMP-0075405-2, "Header, 100mil, 2x1, Gold, TH", Color=Black, Current_A=6.3A, Manufacturer=Samtec, Supplier Part Number 1=SAM1029-02-ND, Voltage_V=550V
L1: library part CMP-0061077-2, "Inductor, Shielded, Composite, 1.5 uH, 7.4 A, 0.0215 ohm, AEC-Q200 Grade 1, SMD", Manufacturer=Coilcraft, Value1="0.0215 ohm", Value2=7.4A, ValueDisplayed=1.5uH
L2 L4: library part CMP-0086402-1, "Shielded Power Inductor,0.47uH, AEC-Q200", Manufacturer=Coilcraft
L3: library part CMP-0087074-1, "Shielded Power Inductors", Manufacturer=Coilcraft
LBL1: library part CMP-0003625-1, "Thermal Transfer Printable Labels, 0.650\" W x 0.200\" H - 10,000 per roll", Manufacturer=Brady, Supplier Part Number 1=97C5133
Logo1: library part CMP-0074844-1
Logo3: library part CMP-0074847-1, "FCC_disclaimer"
Logo4: library part CMP-0074769-1
NT1 NT2 NT3 NT4 NT6 NT7 NT9 NT12: library part CMP-0078142-1, "Single point connection between nets.", Manufacturer=N/A
NT5: library part CMP-0078142-2, "Single point connection between nets.", Manufacturer=N/A
R1 R2 R4 R8 R9 R10 R15 R21 R29: library part CMP-0078779-1, "RES, 10.0 k, 1%, 0.2 W, AEC-Q200 Grade 0, 0402", Manufacturer=Panasonic, Power_W=200mW, Supplier Part Number 1=P17230CT-ND, TempCo="100 ppm/C", Tolerance_%=1%, Value2=0.2W, Value_Code=10k0, ValueDisplayed=10.0k
R3 R5 R13 R18 R25: library part CMP-0026753-1, "RES, 100 k, 1%, 0.063 W, AEC-Q200 Grade 0, 0402", Manufacturer="Stackpole Electronics Inc", Power_W=63mW, Supplier Part Number 1=RMCF0402FT100KCT-ND, TempCo="100 ppm/C", Tolerance_%=1%, Value2=0.063W, Value_Code=100k
R6: library part CMP-0026379-2, "RES, 43.2 k, 1%, 0.063 W, AEC-Q200 Grade 0, 0402", Manufacturer=Vishay-Dale, Power_W=63mW, Supplier Part Number 1=541-43.2KLCT-ND, TempCo="100 ppm/C", Tolerance_%=1%, Value2=0.063W, Value_Code=43k2, ValueDisplayed=43.2k
R7: library part CMP-0026461-2, "RES, 59.0 k, 1%, 0.063 W, AEC-Q200 Grade 0, 0402", Manufacturer=Vishay-Dale, Power_W=63mW, Supplier Part Number 1=541-59.0KLCT-ND, TempCo="100 ppm/C", Tolerance_%=1%, Value2=0.063W, Value_Code=59k0, ValueDisplayed=59.0k
R11: library part CMP-0026570-2, "RES, 80.6 k, 1%, 0.063 W, AEC-Q200 Grade 0, 0402", Manufacturer=Vishay-Dale, Power_W=63mW, Supplier Part Number 1=541-80.6KLCT-ND, TempCo="100 ppm/C", Tolerance_%=1%, Value2=0.063W, Value_Code=80k6, ValueDisplayed=80.6k
R12: library part CMP-0026367-2, "RES, 40.2 k, 1%, 0.063 W, AEC-Q200 Grade 0, 0402", Manufacturer=Vishay-Dale, Power_W=63mW, Supplier Part Number 1=541-40.2KLCT-ND, TempCo="100 ppm/C", Tolerance_%=1%, Value2=0.063W, Value_Code=40k2, ValueDisplayed=40.2k
R14 R19 R26: library part CMP-0026588-2, "RES, 8.06 k, 1%, 0.063 W, AEC-Q200 Grade 0, 0402", Manufacturer=Vishay-Dale, Power_W=63mW, Supplier Part Number 1=541-8.06KLCT-ND, TempCo="100 ppm/C", Tolerance_%=1%, Value2=0.063W, Value_Code=8k06, ValueDisplayed=8.06k
R16: library part CMP-0026586-2, "RES, 88.7 k, 1%, 0.063 W, AEC-Q200 Grade 0, 0402", Manufacturer=Vishay-Dale, Power_W=63mW, Supplier Part Number 1=541-88.7KLCT-ND, TempCo="100 ppm/C", Tolerance_%=1%, Value2=0.063W, Value_Code=88k7, ValueDisplayed=88.7k
R17: library part CMP-0026068-3, "RES, 19.6 k, 1%, 0.063 W, AEC-Q200 Grade 0, 0402", Manufacturer=Vishay-Dale, Power_W=63mW, Supplier Part Number 1=541-19.6KLCT-ND, TempCo="100 ppm/C", Tolerance_%=1%, Value2=0.063W, Value_Code=19k6, ValueDisplayed=19.6k
R20: library part CMP-0026677-1, "RES, 200 k, 1%, 0.1 W, 0402", Manufacturer=Panasonic, Power_W=100mW, Supplier Part Number 1=P200KLCT-ND, TempCo="100 ppm/C", Tolerance_%=1%, Value2=0.1W, Value_Code=200k
R23: library part CMP-0026327-2, "RES, 39.2 k, 1%, 0.063 W, AEC-Q200 Grade 0, 0402", Manufacturer=Vishay-Dale, Power_W=63mW, Supplier Part Number 1=541-39.2KLCT-ND, TempCo="100 ppm/C", Tolerance_%=1%, Value2=0.063W, Value_Code=39k2, ValueDisplayed=39.2k
R24: library part CMP-0026737-1, "RES, 47.0 k, 1%, 0.0625 W, 0402", Manufacturer="Yageo America", Power_W=62.5mW, Supplier Part Number 1=311-47.0KLRCT-ND, TempCo="100 ppm/C", Tolerance_%=1%, Value2=0.0625W, Value_Code=47k0, ValueDisplayed=47.0k
R27: library part CMP-0026353-2, "RES, 3.01, 1%, 0.063 W, AEC-Q200 Grade 0, 0402", Manufacturer=Vishay-Dale, Power_W=63mW, Supplier Part Number 1=541-3.01LLCT-ND, TempCo="100 ppm/C", Tolerance_%=1%, Value2=0.063W, Value_Code=3R01, ValueDisplayed=3.01
R28: library part CMP-0081856-1, "RES, 0, 0%, 0.2 W, AEC-Q200 Grade 0, 0402", Manufacturer=Vishay-Dale, Power_W=200mW, Supplier Part Number 1=541-0.0YBTR-ND, Tolerance_%=0%, Value2=0.2W, Value_Code=0
R30 R31: library part CMP-0026071-3, "RES, 1.00 k, 1%, 0.063 W, AEC-Q200 Grade 0, 0402", Manufacturer=Vishay-Dale, Power_W=63mW, Supplier Part Number 1=541-1.00KLCT-ND, TempCo="100 ppm/C", Tolerance_%=1%, Value2=0.063W, Value_Code=1k00, ValueDisplayed=1.00k
TP1 TP2 TP3 TP4 TP6 TP7 TP9 TP11 TP12: library part CMP-0055160-1, "Test Point, Multipurpose, Purple, TH", Color=Purple, Manufacturer=Keystone, Supplier Part Number 1=36-5129-ND
TP5 TP8 TP10 TP13: library part CMP-0055148-1, "Test Point, Multipurpose, Black, TH", Color=Black, Manufacturer=Keystone, Supplier Part Number 1=36-5011-ND
U1 U3: library part CMP-0073682-2, "5.5V, 4A, 27mO, 2-Ch Automotive Load Switch With Quick Output Discharge and Adjustable Rise Time, DMG0010A (WSON-10)", Alternate Manufacturer="Texas Instruments"
U2: library part CMP-0080079-4, "3.5-V to 36-V, 3.5-A Synchronous Step-Down Voltage Regulator with Spread Spectrum, PWP0016D (TSSOP-16)", Alternate Manufacturer="Texas Instruments", Rating=Automotive
U4 U5 U7: library part CMP-0082642-1, "Automotive Low Input Voltage, Adjustable-Frequency Step-down Converter, RWY0009A (VQFN-HR-9)", Alternate Manufacturer="Texas Instruments", Operating Temperature Range="-40 to 150 C", Rating=Automotive
U6: library part CMP-0066431-3, "Single Bi-Directional Multi-Voltage Level Translator, DRY0006A (USON-6)", Manufacturer="Texas Instruments", Operating Temperature Range="-40 to 125 C", Rating=Catalog

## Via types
v1: diameter 0.5, hole 0.25, Top Layer to Bottom Layer, 72 vias
v2: diameter 0.5, hole 0.2, Top Layer to Bottom Layer, 12 vias
v3: diameter 0.5, hole 0.2, Top Layer to Bottom Layer, tented both sides, 6 vias
v4: diameter 0.5, hole 0.25, Top Layer to Bottom Layer, tented both sides, 1 vias

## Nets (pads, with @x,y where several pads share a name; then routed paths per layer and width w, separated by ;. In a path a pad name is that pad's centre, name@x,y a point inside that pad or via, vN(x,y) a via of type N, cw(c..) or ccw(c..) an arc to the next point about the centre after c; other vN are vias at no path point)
1CT1: C2.1 U1.9 | length 1.1
  Top Layer w0.254: U1.9@52.079,36.276 52.079,35.285 C2.1@52.159,35.205
1CT2: C5.1 U1.7 | length 1.1
  Top Layer w0.254: C5.1@50.899,35.205 51.079,35.385 U1.7@51.079,36.276
1ON_CH1: J1.2 U1.2 | length 30.7
  Top Layer w0.254: U1.2@52.079,38.176 52.093,38.19 52.093,38.64 v1(52.432,38.979)
  Bottom Layer w0.254: v1(52.432,38.979) 56.75,34.662 56.75,18.63 57.629,17.752 J1.2@63.958,17.752
1ON_CH2: J2.2 U1.4 | length 26.5
  Top Layer w0.254: v1(51.062,38.893) 51.079,38.877 U1.4@51.079,38.176
  Bottom Layer w0.254: v1(51.062,38.893) 50.391,38.893 50.052,38.555 50.052,19.147 51.199,18 54.474,18 J2.2@54.724,17.75
1V1_Buck: C14.1 C30.1 C31.1 C32.1 J18.1 L4.2 NT12.1 R23.2 R25.2 R31.2 U3.1 U6.2 | length 47.3
  Top Layer w0.254: v1(70.129,51.542) 70.498,51.173 R25.2@71.186,51.173 ; U3.1@70.497,37.76 U3.1@70.489,37.76 72.128,39.399 C14.1@72.136,39.399 72.136,41.796 C32.1@73.721,43.38 73.724,43.383 C31.1@73.724,45.73 73.878,45.885 L4.2@73.878,47.752 ; v1(79.313,47.514) 78.763,48.064 C30.1@78.663,48.064 78.632,48.096 R23.2@78.632,49.389 83.613,49.389 89.813,55.589 J18.1@93.703,55.589
  Top Layer w0.6: 74.986,40.868 75.286,41.168 R31.2@75.286,41.25
  Signal Layer 2 w0.6: v1@75.817,46.873 77.065,46.873 77.609,46.329 79.927,46.329 v1(81.25,47.652)
  Bottom Layer w0.254: NT12.1@72.678,46.754 72.127,46.754 v1(72.093,46.788) 72.819,47.514 v1(79.313,47.514)
  other v1: 75.703,46.977
1V1_CF: R26.2 U7.7 | length 1.8
  Top Layer w0.254: U7.7@75.942,52.485 75.942,52.521 77.264,52.521 R26.2@77.543,52.799
1V1_CH1: C16.1 J10.1 NT6.1 U3.10 | length 2.8
  Top Layer w0.254: U3.10@70.489,35.86 70.638,35.86 71.039,35.459 71.212,35.459 C16.1@72.093,34.578
  Bottom Layer w0.254: NT6.1@71.016,35.004 71.551,35.004 v1(71.65,34.905)
1V1_EN: J17.2 U7.8 | length 38.2
  Top Layer w0.254: v1@72.984,52.98 v1(72.957,52.953) 72.977,52.932 73.75,52.932 73.942,52.741 U7.8@73.942,52.485
  Bottom Layer w0.254: v1(72.957,52.953) 73.702,53.699 89,53.699 94.53,48.169 94.53,37.524 J17.2@95.953,36.101
1V1_FB: C30.2 R23.1 R24.2 U7.5 | length 4.2
  Top Layer w0.254: U7.5@75.942,50.963 76.219,50.686 R24.2@77.422,50.686 77.422,49.399 R23.1@77.432,49.389 77.432,48.096 C30.2@77.463,48.064
1V1_PG: R25.1 U7.9 | length 1.7
  Top Layer w0.254: R25.1@72.386,51.173 72.421,51.208 72.421,51.694 72.451,51.724 U7.9@73.617,51.724
1V1_Shift: R10.2 R30.1 U6.4 | length 47.7
  Top Layer w0.254: R10.2@35.025,57.371 v1(36.25,57.371) ; v1(73.674,39.651) 73.78,39.544 U6.4@74.442,39.544
  Bottom Layer w0.254: v1(36.25,57.371) 46.374,57.371 53.368,50.377 58.421,50.377 68.853,39.944 73.381,39.944 v1(73.674,39.651) 73.617,39.594 R30.1@73.617,38.727
1V1_SS: C35.1 U7.6 | length 3.5
  Top Layer w0.254: U7.6@76.267,51.724 76.65,51.724 76.993,52.067 78.842,52.067 78.858,52.082 C35.1@78.858,52.799
1V1_SW: L4.1 U7.3@74.942,51.724 | length 3
  Top Layer w0.254: L4.1@73.878,49.552 74.524,49.552 74.942,49.969 U7.3@74.942,51.724
1V8_Buck: C17.1 C20.1 C21.1 C22.1 J13.1 L2.2 NT9.1 R11.2 R13.2 R15.2 U3.5 | length 90.5
  Top Layer w0.254: R15.2@35.22,68.201 v1(36.454,68.201) ; v1(58.5,50.954) 58.568,51.021 R13.2@59.601,51.021 59.601,50.926 60.201,50.326 60.201,47.648 60.267,47.582 L2.2@62.191,47.582 62.191,45.697 C21.1@61.962,45.469 ; v1(60.909,45.069) 61.562,45.069 C21.1@61.962,45.469 ; C20.1@66.957,48.152 66.962,48.157 R11.2@66.962,49.388 ; U3.5@68.489,37.76 66.908,39.342 C17.1@66.908,39.399 65.656,39.399 C22.1@61.967,43.088 61.962,43.093 C21.1@61.962,45.469
  Signal Layer 2 w0.254: J13.1@31.939,43.585 59.426,43.585 v1(60.909,45.069) ; v1(36.454,68.201) 52.114,50.954 v1(58.5,50.954)
  Signal Layer 2 w0.6: v1(60.46,46.534) 60.733,46.807 66.388,46.807 v1(66.963,47.382)
  Bottom Layer w0.254: v1(60.46,46.534) NT9.1@61.036,46.534
  other v1: 60.909,44
1V8_CF: R14.2 U4.7 | length 1.5
  Top Layer w0.254: U4.7@64.312,52.341 65.511,52.341 R14.2@65.727,52.557
1V8_CH2: C18.1 J11.1 NT7.1 U3.6 | length 4.2
  Top Layer w0.254: v1(66.792,33.25) 66.834,33.293 C18.1@66.834,34.355 66.834,34.442 67.852,35.459 68.076,35.459 ; NT7.1@68.076,34.73 68.076,35.459 ; U3.6@68.489,35.86 68.088,35.459 68.076,35.459
1V8_EN: J12.2 U4.8 | length 35.9
  Top Layer w0.254: v1(61.604,53.099) 61.75,52.953 61.75,52.102 ; U4.8@62.312,52.341 U4.8@62.312,52.391
  Bottom Layer w0.254: J12.2@31.584,54.668 31.584,56.83 32.877,58.123 56.199,58.123 61.223,53.099 v1(61.604,53.099)
1V8_FB: C20.2 R11.1 R12.2 U4.5 | length 4
  Top Layer w0.254: U4.5@64.312,50.819 64.504,50.627 R12.2@65.759,50.627 65.759,49.391 R11.1@65.762,49.388 65.762,48.157 C20.2@65.757,48.152
1V8_PG: R13.1 U4.9 | length 1.4
  Top Layer w0.254: R13.1@60.801,51.021 61.046,51.021 61.604,51.58 U4.9@61.987,51.58
1V8_SS: C24.1 U4.6 | length 3
  Top Layer w0.254: U4.6@64.637,51.58 65.02,51.58 65.262,51.821 66.718,51.821 67.026,52.13 C24.1@67.026,52.557
1V8_SW: L2.1 U4.3@63.312,51.58 | length 3
  Top Layer w0.254: L2.1@62.137,49.382 L2.1@62.191,49.382 62.657,49.382 63.312,50.037 U4.3@63.312,51.58
2CT1: C15.1 U3.9 | length 1.2
  Top Layer w0.254: U3.9@69.989,35.86 69.989,35.006 C15.1@70.219,34.776
2CT2: C19.1 U3.7 | length 1.1
  Top Layer w0.254: C19.1@68.9,34.776 68.989,34.866 U3.7@68.989,35.86
2ON_CH1: J8.2 U3.2 | length 32.8
  Top Layer w0.254: U3.2@69.989,37.76 69.989,38.285 v1(70.359,38.654)
  Bottom Layer w0.254: v1(70.359,38.654) 71.214,37.799 72.136,37.799 87,22.935 87,19.373 88.776,17.597 J8.2@91.316,17.597
2ON_CH2: J9.2 U3.4 | length 29.6
  Top Layer w0.254: v1(68.5,38.654) 68.989,38.411 U3.4@68.989,37.76
  Signal Layer 2 w0.254: v1(68.5,38.654) 68.5,38.163 69.276,37.387 70.678,37.387 71.016,37.049 71.016,30.157 78.5,22.673 78.5,19.572 80.45,17.622 81.878,17.622 J9.2@82,17.5
3V3_Buck: C4.1 C26.1 C27.1 C28.1 J16.1 L3.2 R16.2 R18.2 TP11.1 U1.5 | length 38.2
  Top Layer w0.254: J16.1@31.703,31.541 34.196,31.541 42.349,39.693 C4.1@48.985,39.693 ; C4.1@49.061,39.693 C4.1@48.985,39.693 ; v1(52,46.967) 51.568,46.967 50.793,47.742 50.793,45.808 C27.1@50.862,45.739 50.862,43.368 C28.1@50.897,43.333 50.897,41.605 C4.1@48.985,39.693 ; C26.1@55.386,48.448 R16.2@55.386,49.655
  Top Layer w0.5: C4.1@48.982,39.793 U1.5@50.5,38.276
  Signal Layer 2 w0.6: v1(52,46.967) 54.701,46.967 v1(55.386,47.652)
3V3_CF: R19.2 U5.7 | length 1.6
  Top Layer w0.254: U5.7@52.699,52.543 52.807,52.651 R19.2@54.236,52.651
3V3_CH2: C6.1 J4.1 NT2.1 U1.6 | length 26.8
  Top Layer w0.254: J4.1@31.508,19.002 47.284,34.779 C6.1@48.985,34.779 49.987,35.78 ; NT2.1@50.052,35.254 50.052,35.715 49.987,35.78 ; U1.6@50.579,36.276 50.579,36.21 50.149,35.78 49.987,35.78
